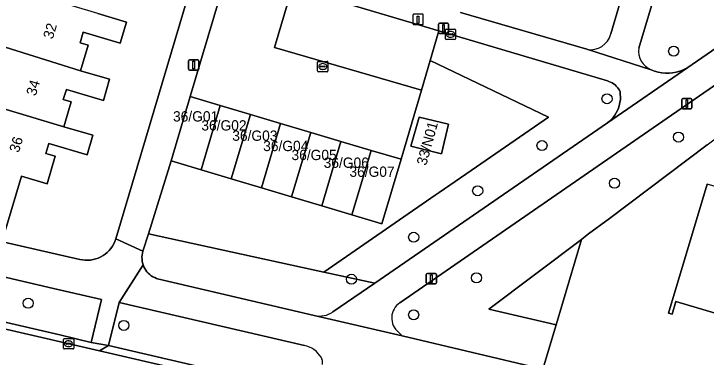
# Model space of a CAD drawing. Extents: x 162184 to 163154, y 385507 to 386516.
# Drawn here: x 162645.2 to 162712.4, y 386003.6 to 386037 of the extents above; entities that cross this region are included whole.
import ezdxf

# ---------------------------------------------------------------- set-up
doc = ezdxf.new("R2010")
doc.units = 0
for name, color, linetype in [('IMGEO_Boom', 7, 'Continuous'), ('IMGEO_Erf', 7, 'Continuous'), ('IMGEO_Groenvoorziening', 7, 'Continuous'), ('IMGEO_Kolk', 7, 'Continuous'), ('IMGEO_Laadpaal', 7, 'Continuous'), ('IMGEO_Lichtmast', 7, 'Continuous'), ('IMGEO_Pand', 7, 'Continuous'), ('IMGEO_Pand_nummerreeks', 7, 'Continuous'), ('IMGEO_Parkeervlak_open', 7, 'Continuous'), ('IMGEO_Rijbaan_lokaal_open', 7, 'Continuous'), ('IMGEO_Voetpad_halfverhard', 7, 'Continuous'), ('IMGEO_Voetpad_open', 7, 'Continuous')]:
    doc.layers.add(name, color=color, linetype=linetype)

msp = doc.modelspace()

# ---------------------------------------------------------------- linework, layer by layer
at = {"layer": 'IMGEO_Boom'}
for centre in [(162709.265, 386033.332), (162702.798, 386028.715), (162709.733, 386024.991), (162696.483, 386024.161), (162703.519, 386020.5), (162690.243, 386019.772), (162684.03, 386015.256), (162677.98, 386011.173), (162690.127, 386011.316), (162646.601, 386008.845), (162684.026, 386007.714), (162655.891, 386006.694)]:
    msp.add_circle(centre, 0.489, dxfattribs=at)
at = {"layer": 'IMGEO_Erf'}
for points in [[(162703.157, 386035.017), (162711.228, 386062.433), (162709.084, 386063.069), (162709.779, 386065.415), (162711.919, 386064.781), (162714.781, 386074.502)], [(162629.257, 386018.226), (162651.623, 386013.1), (162651.878, 386013.05), (162652.137, 386013.022), (162652.397, 386013.018), (162652.656, 386013.038), (162652.913, 386013.08), (162653.165, 386013.145), (162653.41, 386013.232), (162653.646, 386013.341), (162653.871, 386013.47), (162654.084, 386013.619), (162654.283, 386013.787), (162654.466, 386013.971), (162654.632, 386014.172), (162654.78, 386014.386), (162654.907, 386014.613), (162655.014, 386014.85), (162655.1, 386015.095), (162669.961, 386065.071)], [(162688.571, 386037.088), (162700.828, 386033.514)], [(162653.371, 386036.994), (162656.16, 386036.166), (162655.55, 386034.113), (162651.945, 386035.184), (162651.639, 386034.155), (162652.435, 386033.919), (162651.699, 386031.439), (162654.512, 386030.603), (162653.903, 386028.555), (162650.312, 386029.622), (162650.017, 386028.63), (162650.791, 386028.4), (162650.082, 386025.999), (162652.891, 386025.163), (162652.321, 386023.248), (162648.605, 386024.354), (162648.321, 386023.399), (162649.235, 386023.127), (162648.441, 386020.458), (162645.96, 386021.197), (162644.409, 386015.986)], [(162712.504, 386024.226), (162703.022, 386017.084), (162701.015, 386015.572), (162700.507, 386015.189), (162700.318, 386015.047), (162697.849, 386006.759), (162696.564, 386002.448), (162707.015, 386000), (162756.863, 385988.324)], [(162715.918, 386007.089), (162709.48, 386009.012), (162709.112, 386007.781), (162708.771, 386007.883), (162712.514, 386020.419)]]:
    msp.add_lwpolyline(points, dxfattribs=at)
msp.add_arc((162701.198, 386035.496), 2.016, 259.41338, 346.25827, dxfattribs=at)
at = {"layer": 'IMGEO_Groenvoorziening'}
for points in [[(162758.68, 386072.273), (162717.31, 386043.615), (162714.555, 386044.411), (162720.628, 386063.888), (162718.301, 386064.593), (162715.39, 386065.474), (162705.881, 386033.637)], [(162707.08, 386031.526), (162707.413, 386031.401), (162707.756, 386031.307), (162708.106, 386031.243), (162708.46, 386031.211), (162708.816, 386031.211), (162709.17, 386031.242), (162709.52, 386031.305), (162709.863, 386031.4), (162710.196, 386031.524), (162710.517, 386031.677), (162710.65, 386031.752), (162756.796, 386063.642)], [(162682.55, 386006.042), (162682.926, 386005.689), (162696.564, 386002.448), (162697.849, 386006.759), (162691.328, 386008.274), (162700.318, 386015.047), (162700.507, 386015.189), (162701.015, 386015.572), (162703.022, 386017.084), (162712.504, 386024.226), (162722.73, 386031.928), (162718.056, 386033.343), (162682.675, 386008.885)], [(162676.196, 386007.994), (162680.247, 386010.788), (162675.312, 386011.868), (162658.274, 386015.596), (162657.745, 386013.892), (162657.698, 386013.707), (162657.667, 386013.518), (162657.653, 386013.327), (162657.656, 386013.136), (162657.677, 386012.946), (162657.714, 386012.758), (162657.768, 386012.575), (162657.838, 386012.397), (162657.924, 386012.226), (162658.025, 386012.063), (162658.139, 386011.91), (162658.267, 386011.768), (162658.407, 386011.638), (162658.559, 386011.521), (162658.72, 386011.417), (162658.889, 386011.329), (162659.066, 386011.256), (162659.17, 386011.222), (162674.38, 386007.643)], [(162673.421, 386004.742), (162655.429, 386008.924), (162654.412, 386004.751), (162672.324, 386000.567)]]:
    msp.add_lwpolyline(points, dxfattribs=at)
for points in [[(162680.247, 386010.788), (162702.847, 386026.374), (162703.05, 386026.534), (162703.237, 386026.712), (162703.408, 386026.906), (162703.562, 386027.115), (162703.695, 386027.336), (162703.809, 386027.568), (162703.901, 386027.81), (162703.931, 386027.906), (162704.114, 386028.631), (162704.076, 386029.378), (162704.001, 386029.531), (162703.912, 386029.676), (162703.81, 386029.813), (162703.697, 386029.94), (162703.573, 386030.057), (162703.439, 386030.162), (162703.296, 386030.254), (162703.145, 386030.334), (162702.988, 386030.399), (162702.836, 386030.448), (162686.463, 386035.313), (162685.618, 386032.425), (162697.119, 386026.927), (162690.113, 386022.089), (162686.514, 386019.603), (162686.117, 386019.329), (162675.312, 386011.868)], [(162697.119, 386026.927), (162685.618, 386032.425), (162684.772, 386029.534), (162682.811, 386022.827), (162680.949, 386016.57), (162678.023, 386017.441), (162675.097, 386018.312), (162672.172, 386019.182), (162669.247, 386020.053), (162666.321, 386020.924), (162663.396, 386021.794), (162660.47, 386022.665), (162658.274, 386015.596), (162675.312, 386011.868), (162686.117, 386019.329), (162686.514, 386019.603), (162690.113, 386022.089)], [(162683.761, 386024.092), (162684.564, 386026.933), (162687.413, 386026.245), (162686.72, 386023.375)], [(162652.711, 386005.036), (162653.729, 386009.222), (162649.077, 386010.279), (162625.242, 386015.858), (162624.3, 386011.641), (162649.671, 386005.765)], [(162697.849, 386006.759), (162700.318, 386015.047), (162691.328, 386008.274)]]:
    msp.add_lwpolyline(points, close=True, dxfattribs=at)
for centre, radius, start, end in [((162707.859, 386033.364), 1.997, 172.15415, 247.03703), ((162683.659, 386007.417), 1.767, 123.8539, 231.11102), ((162674.854, 386010.066), 2.469, 258.94161, 302.93708), ((162672.858, 386002.203), 2.601, 32.61862, 77.4872), ((162674.007, 386003.053), 1.179, 352.83275, 27.92117)]:
    msp.add_arc(centre, radius, start, end, dxfattribs=at)
at = {"layer": 'IMGEO_Kolk'}
for p, q in [((162687.102, 386034.547), (162687.102, 386035.399)), ((162687.177, 386035.473), (162688.029, 386035.473)), ((162687.404, 386035.016), (162687.802, 386035.016)), ((162687.59, 386035.253), (162687.615, 386035.253)), ((162688.103, 386035.399), (162688.103, 386034.547)), ((162688.029, 386034.473), (162687.177, 386034.473)), ((162687.361, 386034.967), (162687.361, 386034.979)), ((162687.799, 386034.93), (162687.401, 386034.93)), ((162687.613, 386034.693), (162687.588, 386034.693)), ((162687.845, 386034.979), (162687.845, 386034.967)), ((162674.781, 386032.341), (162675.633, 386032.341)), ((162674.706, 386031.415), (162674.706, 386032.267)), ((162674.965, 386031.835), (162674.965, 386031.847)), ((162675.403, 386031.798), (162675.005, 386031.798)), ((162675.008, 386031.884), (162675.406, 386031.884)), ((162675.194, 386032.121), (162675.219, 386032.121)), ((162675.449, 386031.847), (162675.449, 386031.835)), ((162675.707, 386032.267), (162675.707, 386031.415)), ((162675.633, 386031.341), (162674.781, 386031.341)), ((162675.217, 386031.561), (162675.192, 386031.561)), ((162650.028, 386004.48), (162650.028, 386005.332)), ((162650.103, 386005.406), (162650.955, 386005.406)), ((162650.287, 386004.9), (162650.287, 386004.912)), ((162650.725, 386004.863), (162650.327, 386004.863)), ((162650.33, 386004.949), (162650.728, 386004.949)), ((162650.516, 386005.186), (162650.541, 386005.186)), ((162650.771, 386004.912), (162650.771, 386004.9)), ((162651.029, 386005.332), (162651.029, 386004.48)), ((162650.955, 386004.406), (162650.103, 386004.406)), ((162650.539, 386004.626), (162650.514, 386004.626))]:
    msp.add_line(p, q, dxfattribs=at)
for points in [[(162687.102, 386034.547), (162687.102, 386035.399)], [(162687.177, 386035.473), (162688.029, 386035.473)], [(162688.103, 386035.399), (162688.103, 386034.547)], [(162688.029, 386034.473), (162687.177, 386034.473)], [(162674.781, 386032.341), (162675.633, 386032.341)], [(162674.706, 386031.415), (162674.706, 386032.267)], [(162675.707, 386032.267), (162675.707, 386031.415)], [(162675.633, 386031.341), (162674.781, 386031.341)], [(162650.028, 386004.48), (162650.028, 386005.332)], [(162650.103, 386005.406), (162650.955, 386005.406)], [(162651.029, 386005.332), (162651.029, 386004.48)], [(162650.955, 386004.406), (162650.103, 386004.406)]]:
    msp.add_lwpolyline(points, dxfattribs=at)
for centre, radius, start, end in [((162687.179, 386035.397), 0.0765, 91.55205, 178.44795), ((162687.179, 386035.397), 0.0765, 91.55205, 178.44795), ((162687.401, 386034.976), 0.0403, 85.87752, 175.75265), ((162687.806, 386034.978), 0.0386, 1.73085, 96.63898), ((162688.027, 386035.397), 0.0765, 1.55205, 88.44795), ((162688.027, 386035.397), 0.0765, 1.55205, 88.44795), ((162687.179, 386034.549), 0.0765, 181.55205, 268.44795), ((162687.179, 386034.549), 0.0765, 181.55205, 268.44795), ((162687.398, 386034.966), 0.0366, 178.93798, 274.71019), ((162687.802, 386034.973), 0.043, 264.86636, 352.45326), ((162688.027, 386034.549), 0.0765, 271.55205, 358.44795), ((162688.027, 386034.549), 0.0765, 271.55205, 358.44795), ((162674.783, 386032.265), 0.0765, 91.55205, 178.44795), ((162674.783, 386032.265), 0.0765, 91.55205, 178.44795), ((162675.631, 386032.265), 0.0765, 1.55205, 88.44795), ((162675.631, 386032.265), 0.0765, 1.55205, 88.44795), ((162675.005, 386031.844), 0.0403, 85.87752, 175.75265), ((162675.002, 386031.834), 0.0366, 178.93798, 274.71019), ((162675.406, 386031.841), 0.043, 264.86636, 352.45326), ((162675.41, 386031.846), 0.0386, 1.73085, 96.63898), ((162674.783, 386031.417), 0.0765, 181.55205, 268.44795), ((162674.783, 386031.417), 0.0765, 181.55205, 268.44795), ((162675.631, 386031.417), 0.0765, 271.55205, 358.44795), ((162675.631, 386031.417), 0.0765, 271.55205, 358.44795), ((162650.105, 386005.33), 0.0765, 91.55205, 178.44795), ((162650.105, 386005.33), 0.0765, 91.55205, 178.44795), ((162650.327, 386004.909), 0.0403, 85.87752, 175.75265), ((162650.324, 386004.899), 0.0366, 178.93798, 274.71019), ((162650.728, 386004.906), 0.043, 264.86636, 352.45326), ((162650.732, 386004.911), 0.0386, 1.73085, 96.63898), ((162650.953, 386005.33), 0.0765, 1.55205, 88.44795), ((162650.953, 386005.33), 0.0765, 1.55205, 88.44795), ((162650.105, 386004.482), 0.0765, 181.55205, 268.44795), ((162650.105, 386004.482), 0.0765, 181.55205, 268.44795), ((162650.953, 386004.482), 0.0765, 271.55205, 358.44795), ((162650.953, 386004.482), 0.0765, 271.55205, 358.44795)]:
    msp.add_arc(centre, radius, start, end, dxfattribs=at)
for centre, major_axis, ratio, start_param, end_param in [((162687.589, 386034.973), (-0.387, 0.002), 0.722429, 4.712389, 7.853982), ((162687.614, 386034.973), (-0.39, 0.002), 0.717154, 1.570796, 4.712389), ((162675.193, 386031.841), (-0.387, 0.002), 0.722429, 4.712389, 7.853982), ((162675.218, 386031.841), (-0.39, 0.002), 0.717154, 1.570796, 4.712389), ((162650.515, 386004.906), (-0.387, 0.002), 0.722429, 4.712389, 7.853982), ((162650.54, 386004.906), (-0.39, 0.002), 0.717154, 1.570796, 4.712389)]:
    msp.add_ellipse(centre, major_axis=major_axis, ratio=ratio, start_param=start_param, end_param=end_param, dxfattribs=at)
at = {"layer": 'IMGEO_Laadpaal'}
for p, q in [((162683.96, 386036.846), (162683.96, 386036.005)), ((162683.96, 386036.846), (162683.96, 386036.005)), ((162684.876, 386036.93), (162684.035, 386036.93)), ((162684.876, 386036.93), (162684.035, 386036.93)), ((162684.96, 386036.014), (162684.96, 386036.855)), ((162684.96, 386036.014), (162684.96, 386036.855)), ((162684.044, 386035.93), (162684.885, 386035.93)), ((162684.044, 386035.93), (162684.885, 386035.93))]:
    msp.add_line(p, q, dxfattribs=at)
msp.add_lwpolyline([(162684.375, 386036.743), (162684.535, 386036.743), (162684.535, 386036.01), (162684.375, 386036.01), (162684.375, 386036.743)], dxfattribs=at)
for centre, start, end in [((162684.038, 386036.852), 92.4484, 184.28452), ((162684.038, 386036.852), 92.4484, 184.28452), ((162684.882, 386036.852), 2.4484, 94.28452), ((162684.882, 386036.852), 2.4484, 94.28452), ((162684.038, 386036.008), 182.4484, 274.28452), ((162684.038, 386036.008), 182.4484, 274.28452), ((162684.882, 386036.008), 272.4484, 4.28452), ((162684.882, 386036.008), 272.4484, 4.28452)]:
    msp.add_arc(centre, 0.0779, start, end, dxfattribs=at)
at = {"layer": 'IMGEO_Lichtmast'}
for p, q in [((162686.431, 386035.151), (162686.431, 386035.951)), ((162686.431, 386035.951), (162686.431, 386035.151)), ((162686.531, 386036.051), (162687.321, 386036.051)), ((162687.321, 386036.051), (162686.531, 386036.051)), ((162687.421, 386035.951), (162687.421, 386035.151)), ((162687.421, 386035.151), (162687.421, 386035.951)), ((162687.321, 386035.051), (162686.531, 386035.051)), ((162686.531, 386035.051), (162687.321, 386035.051)), ((162662.18, 386031.589), (162662.18, 386032.389)), ((162662.18, 386032.389), (162662.18, 386031.589)), ((162662.28, 386032.489), (162663.07, 386032.489)), ((162663.07, 386032.489), (162662.28, 386032.489)), ((162663.17, 386032.389), (162663.17, 386031.589)), ((162663.17, 386031.589), (162663.17, 386032.389)), ((162663.07, 386031.489), (162662.28, 386031.489)), ((162662.28, 386031.489), (162663.07, 386031.489)), ((162710.048, 386027.842), (162710.048, 386028.642)), ((162710.048, 386028.642), (162710.048, 386027.842)), ((162710.148, 386028.742), (162710.938, 386028.742)), ((162710.938, 386028.742), (162710.148, 386028.742)), ((162711.038, 386028.642), (162711.038, 386027.842)), ((162711.038, 386027.842), (162711.038, 386028.642)), ((162710.938, 386027.742), (162710.148, 386027.742)), ((162710.148, 386027.742), (162710.938, 386027.742)), ((162685.255, 386010.834), (162685.255, 386011.634)), ((162685.255, 386011.634), (162685.255, 386010.834)), ((162685.355, 386011.734), (162686.145, 386011.734)), ((162686.145, 386011.734), (162685.355, 386011.734)), ((162686.245, 386011.634), (162686.245, 386010.834)), ((162686.245, 386010.834), (162686.245, 386011.634)), ((162686.145, 386010.734), (162685.355, 386010.734)), ((162685.355, 386010.734), (162686.145, 386010.734))]:
    msp.add_line(p, q, dxfattribs=at)
for points in [[(162686.851, 386035.926), (162687.001, 386035.926), (162687.001, 386035.176), (162686.851, 386035.176), (162686.851, 386035.926)], [(162662.6, 386032.364), (162662.75, 386032.364), (162662.75, 386031.614), (162662.6, 386031.614), (162662.6, 386032.364)], [(162710.468, 386028.617), (162710.618, 386028.617), (162710.618, 386027.867), (162710.468, 386027.867), (162710.468, 386028.617)], [(162685.675, 386011.609), (162685.825, 386011.609), (162685.825, 386010.859), (162685.675, 386010.859), (162685.675, 386011.609)]]:
    msp.add_lwpolyline(points, dxfattribs=at)
for centre, start, end in [((162686.531, 386035.951), 90, 180), ((162686.531, 386035.951), 90, 180), ((162687.321, 386035.951), 0, 90), ((162687.321, 386035.951), 360, 90), ((162686.531, 386035.151), 180, 270), ((162686.531, 386035.151), 180, 270), ((162687.321, 386035.151), 270, 0), ((162687.321, 386035.151), 270, 0), ((162662.28, 386032.389), 90, 180), ((162662.28, 386032.389), 90, 180), ((162663.07, 386032.389), 0, 90), ((162663.07, 386032.389), 360, 90), ((162662.28, 386031.589), 180, 270), ((162662.28, 386031.589), 180, 270), ((162663.07, 386031.589), 270, 0), ((162663.07, 386031.589), 270, 0), ((162710.148, 386028.642), 90, 180), ((162710.148, 386028.642), 90, 180), ((162710.938, 386028.642), 0, 90), ((162710.938, 386028.642), 360, 90), ((162710.148, 386027.842), 180, 270), ((162710.148, 386027.842), 180, 270), ((162710.938, 386027.842), 270, 0), ((162710.938, 386027.842), 270, 0), ((162685.355, 386011.634), 90, 180), ((162685.355, 386011.634), 90, 180), ((162686.145, 386011.634), 0, 90), ((162686.145, 386011.634), 360, 90), ((162685.355, 386010.834), 180, 270), ((162685.355, 386010.834), 180, 270), ((162686.145, 386010.834), 270, 0), ((162686.145, 386010.834), 270, 0)]:
    msp.add_arc(centre, 0.1, start, end, dxfattribs=at)
at = {"layer": 'IMGEO_Pand'}
for points in [[(162656.16, 386036.166), (162653.371, 386036.994), (162643.704, 386039.91), (162643.638, 386039.687), (162643.322, 386039.781), (162642.461, 386036.887), (162642.769, 386036.795), (162642.068, 386034.437), (162651.699, 386031.439), (162652.435, 386033.919), (162651.639, 386034.155), (162651.945, 386035.184), (162655.55, 386034.113)], [(162641.141, 386034.713), (162639.171, 386035.299), (162637.515, 386029.731), (162639.486, 386029.145), (162650.082, 386025.999), (162650.791, 386028.4), (162650.017, 386028.63), (162650.312, 386029.622), (162653.903, 386028.555), (162654.512, 386030.603), (162651.699, 386031.439), (162642.068, 386034.437)], [(162639.405, 386028.874), (162640.043, 386028.685), (162639.192, 386025.828), (162639.448, 386025.752), (162638.752, 386023.411), (162635.313, 386024.435), (162633.744, 386019.161), (162644.409, 386015.986), (162645.96, 386021.197), (162648.441, 386020.458), (162649.235, 386023.127), (162648.321, 386023.399), (162648.605, 386024.354), (162652.321, 386023.248), (162652.891, 386025.163), (162650.082, 386025.999), (162639.486, 386029.145)], [(162660.47, 386022.665), (162663.396, 386021.794), (162665.258, 386028.052), (162662.333, 386028.923)], [(162665.258, 386028.052), (162663.396, 386021.794), (162666.321, 386020.924), (162668.184, 386027.181)], [(162668.184, 386027.181), (162666.321, 386020.924), (162669.247, 386020.053), (162671.109, 386026.31)], [(162671.109, 386026.31), (162669.247, 386020.053), (162672.172, 386019.182), (162674.035, 386025.44)], [(162683.761, 386024.092), (162686.72, 386023.375), (162687.413, 386026.245), (162684.564, 386026.933)], [(162674.035, 386025.44), (162672.172, 386019.182), (162675.097, 386018.312), (162676.96, 386024.569)], [(162676.96, 386024.569), (162675.097, 386018.312), (162678.023, 386017.441), (162679.886, 386023.698)], [(162679.886, 386023.698), (162678.023, 386017.441), (162680.949, 386016.57), (162682.811, 386022.827)], [(162718.824, 386014.942), (162713.804, 386016.441), (162713.857, 386016.619), (162713.686, 386016.67), (162714.618, 386019.79), (162712.514, 386020.419), (162708.771, 386007.883), (162709.112, 386007.781), (162709.48, 386009.012), (162715.918, 386007.089), (162715.841, 386006.831), (162716.356, 386006.677)]]:
    msp.add_lwpolyline(points, close=True, dxfattribs=at)
at = {"layer": 'IMGEO_Parkeervlak_open'}
msp.add_lwpolyline([(162686.463, 386035.313), (162675.766, 386038.532), (162675.556, 386038.602), (162675.134, 386038.773), (162674.729, 386038.982), (162674.344, 386039.226), (162673.983, 386039.504), (162673.648, 386039.813), (162673.342, 386040.15), (162673.067, 386040.513), (162672.826, 386040.9), (162672.704, 386041.141), (162670.528, 386033.7), (162684.772, 386029.534), (162685.618, 386032.425)], close=True, dxfattribs=at)
at = {"layer": 'IMGEO_Rijbaan_lokaal_open'}
for points in [[(162687.061, 386094.431), (162682.265, 386095.831), (162662.333, 386028.923), (162665.258, 386028.052), (162668.184, 386027.181), (162671.109, 386026.31), (162674.035, 386025.44), (162676.96, 386024.569), (162679.886, 386023.698), (162682.811, 386022.827), (162684.772, 386029.534), (162670.528, 386033.7), (162672.704, 386041.141), (162672.62, 386041.307), (162672.451, 386041.73), (162672.321, 386042.167), (162672.23, 386042.613), (162672.18, 386043.066), (162672.17, 386043.522), (162672.201, 386043.976), (162672.273, 386044.426), (162672.384, 386044.868)], [(162671.697, 386000), (162653.515, 386004.211), (162635.584, 386008.379), (162633.981, 386001.479), (162638.145, 386000.504), (162640.314, 386000), (162644.966, 385998.919), (162652.104, 385997.26), (162660.336, 385995.367), (162667.647, 385993.685), (162682.431, 385990.285), (162687.936, 385989.019), (162705.604, 385984.92), (162709.674, 385983.966), (162714.417, 385982.854), (162716.011, 385989.658)]]:
    msp.add_lwpolyline(points, close=True, dxfattribs=at)
at = {"layer": 'IMGEO_Voetpad_halfverhard'}
for points in [[(162682.675, 386008.885), (162718.056, 386033.343), (162721.276, 386035.605), (162737.255, 386046.591), (162754.435, 386058.403), (162761.276, 386063.106), (162757.426, 386064.259), (162756.796, 386063.642), (162710.65, 386031.752), (162702.847, 386026.374), (162680.247, 386010.788), (162676.196, 386007.994)], [(162674.38, 386007.643), (162682.926, 386005.689), (162682.55, 386006.042)]]:
    msp.add_lwpolyline(points, dxfattribs=at)
for centre, radius, start, end in [((162683.659, 386007.417), 1.767, 123.8539, 231.11102), ((162674.854, 386010.066), 2.469, 258.94161, 302.93708)]:
    msp.add_arc(centre, radius, start, end, dxfattribs=at)
at = {"layer": 'IMGEO_Voetpad_open'}
for points in [[(162705.881, 386033.637), (162715.39, 386065.474), (162717.243, 386071.595), (162725.891, 386100.255), (162730.846, 386117.114)], [(162723.787, 386104.88), (162721.438, 386096.954), (162721.377, 386096.799), (162718.363, 386086.601), (162718.43, 386086.581), (162717.88, 386084.724), (162717.814, 386084.744), (162715.637, 386077.378), (162714.781, 386074.502), (162711.919, 386064.781), (162712.041, 386064.745), (162711.346, 386062.398), (162711.228, 386062.433), (162703.157, 386035.017)], [(162678.454, 386093.552), (162675.341, 386083.069), (162673.803, 386077.892), (162672.402, 386073.174), (162670.024, 386065.332), (162669.961, 386065.071), (162655.1, 386015.095), (162657.745, 386013.892), (162658.274, 386015.596), (162660.47, 386022.665), (162662.333, 386028.923), (162682.265, 386095.831)], [(162675.766, 386038.532), (162686.463, 386035.313), (162702.836, 386030.448), (162702.988, 386030.399), (162703.145, 386030.334), (162703.296, 386030.254), (162703.439, 386030.162), (162703.573, 386030.057), (162703.697, 386029.94), (162703.81, 386029.813), (162703.912, 386029.676), (162704.001, 386029.531), (162704.076, 386029.378), (162704.114, 386028.631), (162703.931, 386027.906), (162703.901, 386027.81), (162703.809, 386027.568), (162703.695, 386027.336), (162703.562, 386027.115), (162703.408, 386026.906), (162703.237, 386026.712), (162703.05, 386026.534), (162702.847, 386026.374), (162710.65, 386031.752), (162710.517, 386031.677), (162710.196, 386031.524), (162709.863, 386031.4), (162709.52, 386031.305), (162709.17, 386031.242), (162708.816, 386031.211), (162708.46, 386031.211), (162708.106, 386031.243), (162707.756, 386031.307), (162707.413, 386031.401), (162707.08, 386031.526), (162700.828, 386033.514), (162688.571, 386037.088)], [(162700.828, 386033.514), (162707.08, 386031.526)], [(162625.242, 386015.858), (162649.077, 386010.279), (162653.729, 386009.222), (162652.711, 386005.036), (162654.412, 386004.751), (162655.429, 386008.924), (162657.768, 386012.575), (162657.714, 386012.758), (162657.677, 386012.946), (162657.656, 386013.136), (162657.653, 386013.327), (162657.667, 386013.518), (162657.698, 386013.707), (162657.745, 386013.892), (162655.1, 386015.095), (162655.014, 386014.85), (162654.907, 386014.613), (162654.78, 386014.386), (162654.632, 386014.172), (162654.466, 386013.971), (162654.283, 386013.787), (162654.084, 386013.619), (162653.871, 386013.47), (162653.646, 386013.341), (162653.41, 386013.232), (162653.165, 386013.145), (162652.913, 386013.08), (162652.656, 386013.038), (162652.397, 386013.018), (162652.137, 386013.022), (162651.878, 386013.05), (162651.623, 386013.1), (162629.257, 386018.226)], [(162659.17, 386011.222), (162659.066, 386011.256), (162658.889, 386011.329), (162658.72, 386011.417), (162658.559, 386011.521), (162658.407, 386011.638), (162658.267, 386011.768), (162658.139, 386011.91), (162658.025, 386012.063), (162657.924, 386012.226), (162657.838, 386012.397), (162657.768, 386012.575), (162655.429, 386008.924), (162673.421, 386004.742)], [(162757.945, 385983.903), (162757.702, 385982.634), (162757.537, 385982.185), (162757.068, 385980.076), (162759.758, 385979.448), (162759.873, 385979.94), (162765.2, 385978.691), (162767.082, 385985.941), (162762.348, 385987.291), (162758.422, 385988.351), (162756.863, 385988.324), (162707.015, 386000), (162696.564, 386002.448), (162682.926, 386005.689), (162674.38, 386007.643), (162659.17, 386011.222)], [(162679.477, 385998.729), (162679.372, 385998.748), (162672.499, 386000.509), (162672.324, 386000.567), (162654.412, 386004.751), (162653.515, 386004.211), (162671.697, 386000), (162716.011, 385989.658), (162720.741, 385988.554), (162757.068, 385980.076), (162757.537, 385982.185)]]:
    msp.add_lwpolyline(points, dxfattribs=at)
msp.add_lwpolyline([(162624.3, 386011.641), (162622.672, 386012.006), (162548.585, 386029.344), (162549.167, 386028.469), (162630.86, 386009.478), (162635.584, 386008.379), (162653.515, 386004.211), (162654.412, 386004.751), (162652.711, 386005.036), (162649.671, 386005.765)], close=True, dxfattribs=at)
for centre, radius, start, end in [((162701.198, 386035.496), 2.016, 259.41338, 346.25827), ((162707.859, 386033.364), 1.997, 172.15415, 247.03703), ((162672.858, 386002.203), 2.601, 32.61862, 77.4872), ((162674.007, 386003.053), 1.179, 352.83275, 27.92117)]:
    msp.add_arc(centre, radius, start, end, dxfattribs=at)

# ---------------------------------------------------------------- texts
at = {"layer": 'IMGEO_Pand_nummerreeks'}
for s, rotation, p in [('32', 73.3787, (162648.988, 386034.444)), ('34', 73.38081, (162647.343, 386028.932)), ('33/N01', 74.6001, (162685.253, 386022.169)), ('36', 73.38081, (162645.697, 386023.417))]:
    msp.add_text(s, height=1, rotation=rotation, dxfattribs=at).set_placement(p)
for s, p in [('36/G01', (162660.667, 386026.5)), ('36/G02', (162663.417, 386025.625)), ('36/G03', (162666.417, 386024.625)), ('36/G04', (162669.417, 386023.625)), ('36/G05', (162672.167, 386022.75)), ('36/G06', (162675.292, 386022)), ('36/G07', (162677.792, 386021.125))]:
    msp.add_text(s, height=1, dxfattribs=at).set_placement(p)

doc.saveas('drawing.dxf')
